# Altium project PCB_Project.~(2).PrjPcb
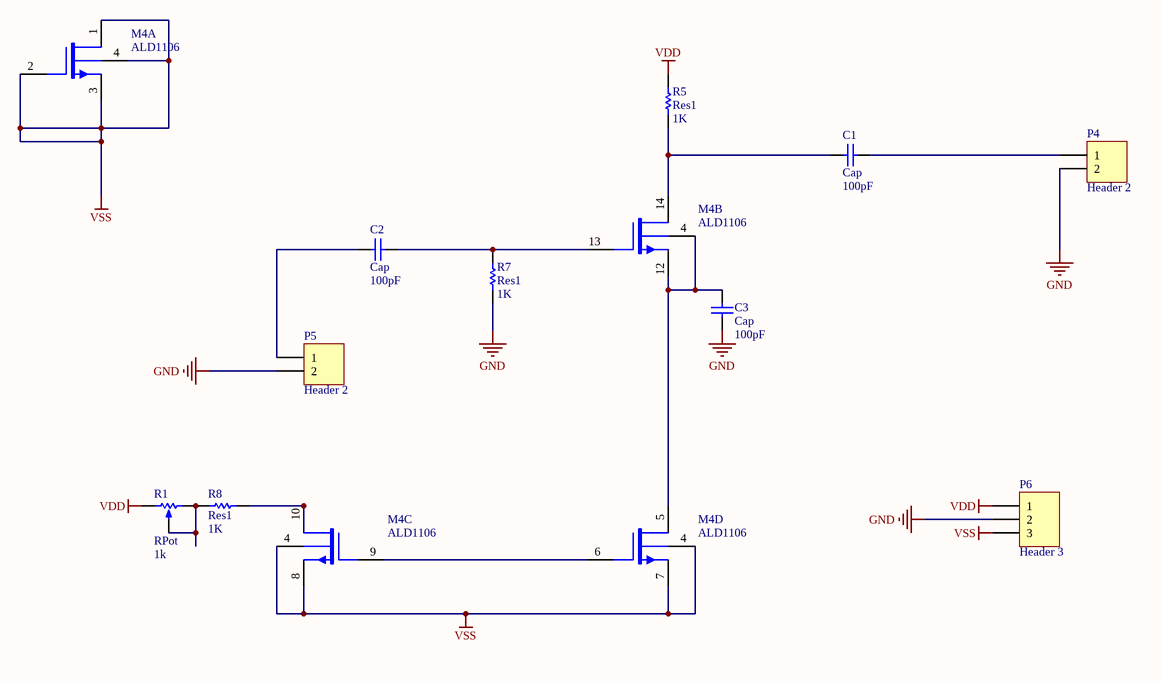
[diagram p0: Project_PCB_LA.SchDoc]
1 sheet, 11 parts. Net scope: global (net labels, ports and power ports of the same name join across sheets).
Board file: PCB3_LA.PcbDoc

## Sheet Project_PCB_LA.SchDoc
size A4

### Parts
C1  Cap  value 100pF  [RAD-0.3]
C2  Cap  value 100pF  [RAD-0.3]
C3  Cap  value 100pF  [RAD-0.3]
M4  ALD1106  [DIP-14]  (parts A,B,C,D of 4)
P4  Header 2  [HDR1X2]
P5  Header 2  [HDR1X2]
P6  Header 3  [HDR1X3]
R1  RPot  value 1k  [VR5]
R5  Res1  value 1K  [AXIAL-0.3]
R7  Res1  value 1K  [AXIAL-0.3]
R8  Res1  value 1K  [AXIAL-0.3]

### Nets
GND: C3.2 P4.2 P5.2 P6.2 R7.2
VDD: P6.1 R1.1(TOP) R5.2
VSS: M4.1(DN1) M4.2(GN1) M4.3(SN1) M4.4(V-) M4.7(SN4) M4.8(SN3) P6.3
NetC1_1: C1.1 P4.1
NetC1_2: C1.2 M4.14(DN2) R5.1
NetC2_1: C2.1 P5.1
NetC2_2: C2.2 M4.13(GN2) R7.1
NetC3_1: C3.1 M4.4(V-) M4.5(DN4) M4.12(SN2)
NetM4_6: M4.6(GN4) M4.9(GN3)
NetM4_10: M4.10(DN3) R8.1
NetR1_2: R1.2(TAP) R1.3(BOT) R8.2

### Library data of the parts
C1-C3 = Cap: Capacitor
M4 = ALD1106: Quad N-channel matched MOSFET array
P4 P5 = Header 2: Header, 2-Pin
P6 = Header 3: Header, 3-Pin
R1 = RPot: Potentiometer; Sim Note: Enter the Resistance value and the set point into parameter fields.; Set Position: 0.5
R5 R7 R8 = Res1: Resistor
